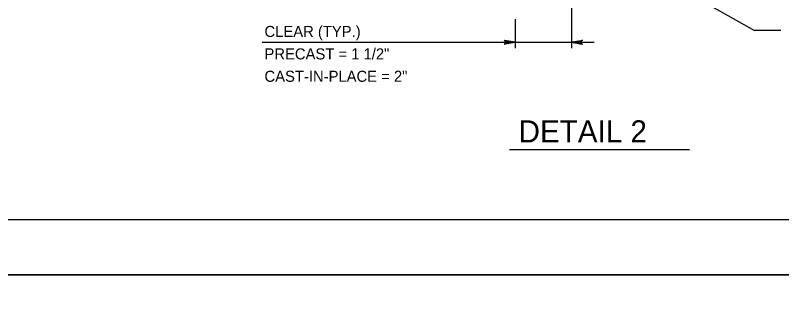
# Model space of a CAD drawing. Extents: x 2087776 to 2104538, y 970919 to 982612.
# Drawn here: x 2094288 to 2094970, y 972844 to 973099 of the extents above; entities that cross this region are included whole.
import ezdxf

# ---------------------------------------------------------------- set-up
doc = ezdxf.new("R2010")
doc.units = 0
doc.layers.add('1', color=7, linetype='Continuous')
doc.layers.add('PLT-BNDY', color=7, linetype='Continuous')

msp = doc.modelspace()

# ---------------------------------------------------------------- linework, layer by layer
at = {"layer": '1'}
for p, q in [((2094795.05, 973170.64), (2094945.36, 973085.34)), ((2094782.55, 973134.97), (2094782.55, 973069.81)), ((2094732.55, 973095.41), (2094732.55, 973069.81)), ((2094969.03, 973085.34), (2094945.36, 973085.34)), ((2094507.52, 973075.01), (2094802.88, 973075.01)), ((2094727.51, 972979.54), (2094887.75, 972979.54))]:
    msp.add_line(p, q, dxfattribs=at)
for points in [[(2096000.74, 972917.37), (2096000.74, 974767.76), (2093422, 974767.76), (2093422, 972917.37), (2096000.74, 972917.37), (2096000.74, 973003.85), (2095344.57, 973003.85), (2095344.57, 973216.04), (2096000.74, 973216.04), (2096000.74, 973311.07), (2095344.57, 973311.07), (2095344.57, 972917.37), (2095603.11, 972917.37), (2095603.11, 973003.85), (2095603.11, 972917.37), (2095855.73, 972917.37), (2095855.73, 973003.85), (2095855.73, 972963.44), (2096000.74, 972963.44)], [(2094732.55, 973075.01), (2094722.76, 973073.17), (2094723.14, 973073.43), (2094723.52, 973073.69), (2094723.71, 973074.02), (2094723.91, 973074.35), (2094723.96, 973074.68), (2094724.02, 973075.01), (2094723.96, 973075.33), (2094723.91, 973075.66), (2094723.71, 973075.99), (2094723.52, 973076.32), (2094723.14, 973076.58), (2094722.76, 973076.84), (2094732.55, 973075.01), (2094723.14, 973076.58), (2094723.52, 973076.32), (2094732.55, 973075.01), (2094723.71, 973075.99), (2094723.91, 973075.66), (2094732.55, 973075.01), (2094723.96, 973075.33), (2094724.02, 973075.01), (2094732.55, 973075.01), (2094723.96, 973074.68), (2094723.91, 973074.35), (2094732.55, 973075.01), (2094723.71, 973074.02), (2094723.52, 973073.69), (2094732.55, 973075.01), (2094723.14, 973073.43)], [(2094782.55, 973075.01), (2094792.34, 973076.84), (2094791.96, 973076.58), (2094791.58, 973076.32), (2094791.39, 973075.99), (2094791.19, 973075.66), (2094791.14, 973075.33), (2094791.08, 973075.01), (2094791.14, 973074.68), (2094791.19, 973074.35), (2094791.39, 973074.02), (2094791.58, 973073.69), (2094791.96, 973073.43), (2094792.34, 973073.17), (2094782.55, 973075.01), (2094791.96, 973073.43), (2094791.58, 973073.69), (2094782.55, 973075.01), (2094791.39, 973074.02), (2094791.19, 973074.35), (2094782.55, 973075.01), (2094791.14, 973074.68), (2094791.08, 973075.01), (2094782.55, 973075.01), (2094791.14, 973075.33), (2094791.19, 973075.66), (2094782.55, 973075.01), (2094791.39, 973075.99), (2094791.58, 973076.32), (2094782.55, 973075.01), (2094791.96, 973076.58)]]:
    msp.add_lwpolyline(points, dxfattribs=at)
at = {"layer": 'PLT-BNDY'}
for points in [[(2093294.05, 974816.97), (2096053.23, 974816.97), (2096053.23, 972868.16), (2093294.05, 972868.16)], [(2093294.05, 972868.16), (2096053.23, 972868.16), (2096053.23, 970919.34), (2093294.05, 970919.34)]]:
    msp.add_lwpolyline(points, close=True, dxfattribs=at)

# ---------------------------------------------------------------- texts
at = {"layer": '1'}
for s, height, p in [('CLEAR (TYP.)', 9.8425, (2094509.48, 973079.68)), ('PRECAST = 1 1/2"', 9.8425, (2094509.48, 973059.76)), ('CAST-IN-PLACE = 2" ', 9.8425, (2094509.48, 973039.84)), ('DETAIL 2', 19.685, (2094735.62, 972985.94))]:
    msp.add_text(s, height=height, dxfattribs=at).set_placement(p)

doc.saveas('drawing.dxf')
